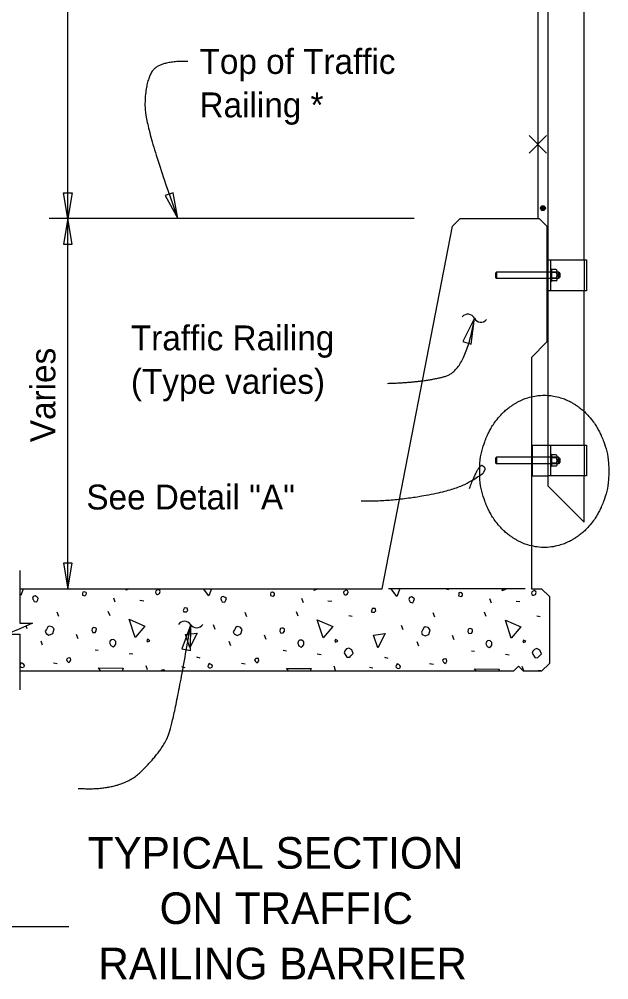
# Model space of a CAD drawing. Extents: x 0 to 41.1, y 0 to 25.9.
# Drawn here: x 29.01 to 33.79, y 11.06 to 18.84 of the extents above; entities that cross this region are included whole.
import ezdxf

# ---------------------------------------------------------------- set-up
doc = ezdxf.new("R2010")
doc.units = 0
for name, color, linetype in [('Dimension', 7, 'Continuous'), ('Miscellaneous', 7, 'Continuous'), ('SteelMisc', 7, 'Continuous'), ('SteelMisc_h', 7, 'Continuous'), ('SupstrConc', 7, 'Continuous'), ('SupstrConc_h', 7, 'Continuous'), ('TextStructures', 7, 'Continuous'), ('TrafBarrierConc', 7, 'Continuous')]:
    doc.layers.add(name, color=color, linetype=linetype)

msp = doc.modelspace()

# ---------------------------------------------------------------- linework, layer by layer
at = {"layer": 'Dimension'}
for p, q in [((29.4061, 14.2246), (29.4061, 23.2246)), ((32.214, 17.2246), (29.2561, 17.2246)), ((23.6151, 11.4901), (29.4153, 11.4901))]:
    msp.add_line(p, q, dxfattribs=at)
for points in [[(29.4061, 17.2246), (29.3708, 17.4328), (29.4413, 17.4328)], [(30.2977, 17.2246), (30.2616, 17.4327), (30.1951, 17.4092)], [(29.4061, 17.2246), (29.3708, 17.0163), (29.4413, 17.0163)], [(32.7026, 16.4167), (32.6085, 16.2276), (32.676, 16.2071)], [(29.4061, 14.2246), (29.4413, 14.4328), (29.3708, 14.4328)], [(30.403, 13.937), (30.3312, 13.7384), (30.4006, 13.7258)]]:
    msp.add_lwpolyline(points, close=True, dxfattribs=at)
msp.add_lwpolyline([(29.0176, 14.3746), (29.0176, 13.9474), (29.1209, 13.9474), (29.0176, 13.9024), (28.9142, 13.8574), (29.0176, 13.8574), (29.0176, 13.4079)], dxfattribs=at)
for centre, start, end in [((32.6489, 16.3894), 27.32823, 139.05545), ((32.7548, 16.4441), 207.32823, 319.05545), ((30.3527, 13.9038), 33.91896, 145.64618), ((30.4517, 13.9703), 213.91896, 325.64618)]:
    msp.add_arc(centre, 0.0596, start, end, dxfattribs=at)
for points, degree in [([(30.3802, 18.496), (30.1383, 18.5019), (30.0322, 18.3129), (30.0322, 17.9586), (30.2976, 17.2245)], 2), ([(31.9983, 15.889), (32.2959, 15.8977), (32.6322, 15.993), (32.7026, 16.4166)], 2), ([(33.2678, 14.5608), (33.3028, 14.5608), (33.3375, 14.5649), (33.4054, 14.5811), (33.4386, 14.5931), (33.4864, 14.6167), (33.502, 14.6255), (33.5248, 14.64), (33.5323, 14.6451), (33.5471, 14.6557), (33.5543, 14.6612), (33.5899, 14.6896), (33.6163, 14.7155), (33.6642, 14.7726), (33.6856, 14.8038), (33.7091, 14.8457), (33.7136, 14.8542), (33.7223, 14.8715), (33.7265, 14.8803), (33.7384, 14.9069), (33.7456, 14.9251), (33.7776, 15.0175), (33.7909, 15.0966), (33.7909, 15.2569), (33.7776, 15.336), (33.7456, 15.4283), (33.7384, 15.4465), (33.7265, 15.4731), (33.7223, 15.4819), (33.7136, 15.4992), (33.7091, 15.5077), (33.6856, 15.5496), (33.6642, 15.5808), (33.6163, 15.638), (33.5899, 15.6638), (33.5543, 15.6923), (33.5471, 15.6978), (33.5323, 15.7083), (33.5248, 15.7134), (33.502, 15.7279), (33.4864, 15.7367), (33.4386, 15.7603), (33.4054, 15.7724), (33.3375, 15.7885), (33.3028, 15.7926), (33.2328, 15.7926), (33.198, 15.7885), (33.1301, 15.7724), (33.097, 15.7603), (33.0492, 15.7367), (33.0336, 15.7279), (33.0108, 15.7134), (33.0033, 15.7083), (32.9885, 15.6978), (32.9812, 15.6923), (32.9456, 15.6638), (32.9193, 15.638), (32.8714, 15.5808), (32.8499, 15.5496), (32.8264, 15.5077), (32.8219, 15.4992), (32.8132, 15.4819), (32.8091, 15.4731), (32.7971, 15.4465), (32.79, 15.4283), (32.7579, 15.336), (32.7447, 15.2569), (32.7447, 15.0966), (32.7579, 15.0175), (32.79, 14.9251), (32.7971, 14.9069), (32.8091, 14.8803), (32.8132, 14.8715), (32.8219, 14.8542), (32.8264, 14.8457), (32.8499, 14.8038), (32.8714, 14.7726), (32.9193, 14.7155), (32.9456, 14.6896), (32.9812, 14.6612), (32.9885, 14.6557), (33.0033, 14.6451), (33.0108, 14.64), (33.0336, 14.6255), (33.0492, 14.6167), (33.097, 14.5931), (33.1301, 14.5811), (33.198, 14.5649), (33.2328, 14.5608), (33.2678, 14.5608)], 3), ([(31.785, 14.9372), (32.0075, 14.9325), (32.5443, 15.0224), (32.7693, 15.1547), (32.78, 15.1766), (32.7962, 15.2026), (32.737, 15.2403), (32.6589, 15.0361)], 2), ([(29.4916, 12.6094), (29.8372, 12.5861), (30.1609, 12.9013), (30.2688, 13.1436), (30.4029, 13.9374)], 2)]:
    msp.add_open_spline(points, degree=degree, dxfattribs=at)
at = {"layer": 'Miscellaneous'}
for p, q in [((33.2861, 17.8952), (33.1447, 17.7539)), ((33.1447, 17.8952), (33.2861, 17.7539)), ((33.2884, 16.8894), (33.2988, 16.8894)), ((33.292, 16.8894), (33.292, 16.6394)), ((33.2953, 16.8894), (33.2953, 16.6394)), ((33.3795, 16.7756), (33.3795, 16.7548)), ((33.3891, 16.7756), (33.3891, 16.7548)), ((33.2988, 16.6394), (33.2884, 16.6394)), ((33.1634, 15.3894), (33.1738, 15.3894)), ((33.167, 15.3894), (33.167, 15.1394)), ((33.1703, 15.3894), (33.1703, 15.1394)), ((33.3795, 15.2756), (33.3795, 15.2548)), ((33.3891, 15.2756), (33.3891, 15.2548)), ((33.1738, 15.1394), (33.1634, 15.1394)), ((30.9661, 14.2246), (30.9674, 14.2243)), ((32.4722, 14.2246), (32.4912, 14.2207)), ((29.7919, 14.1165), (29.7795, 14.15)), ((29.9916, 14.1324), (30.0234, 14.1288)), ((31.3157, 14.1129), (31.3033, 14.1465)), ((31.5154, 14.1288), (31.5473, 14.1253)), ((32.8395, 14.1094), (32.8271, 14.143)), ((33.0392, 14.1253), (33.0711, 14.1218)), ((29.334, 14.0015), (29.3199, 14.0369)), ((29.7494, 14.0068), (29.7353, 14.0422)), ((30.8578, 13.998), (30.8437, 14.0334)), ((31.2732, 14.0033), (31.2591, 14.0387)), ((31.6834, 14.0104), (31.7117, 14.0033)), ((32.3816, 13.9945), (32.3675, 14.0298)), ((32.7971, 13.9998), (32.7829, 14.0351)), ((33.2072, 14.0068), (33.2355, 13.9998)), ((29.0777, 13.9008), (29.0682, 13.9245)), ((30.6015, 13.8972), (30.5874, 13.9326)), ((32.1253, 13.8937), (32.1112, 13.9291)), ((29.4913, 13.8195), (29.4772, 13.8548)), ((31.0152, 13.8159), (31.001, 13.8513)), ((32.539, 13.8124), (32.5248, 13.8477)), ((29.2032, 13.7682), (29.1908, 13.8018)), ((30.727, 13.7647), (30.7146, 13.7983)), ((32.2508, 13.7611), (32.2384, 13.7947)), ((29.6292, 13.7311), (29.654, 13.7275)), ((29.905, 13.7028), (29.935, 13.6975)), ((31.153, 13.7275), (31.1778, 13.724)), ((31.4288, 13.6993), (31.4589, 13.694)), ((32.6769, 13.724), (32.7016, 13.7205)), ((32.9526, 13.6957), (32.9827, 13.6904)), ((29.2916, 13.6268), (29.3216, 13.6215)), ((30.4495, 13.6745), (30.4778, 13.6674)), ((30.8154, 13.6232), (30.8454, 13.6179)), ((31.9733, 13.671), (32.0016, 13.6639)), ((32.3392, 13.6197), (32.3693, 13.6144)), ((30.0535, 13.5684), (30.0411, 13.602)), ((30.3275, 13.595), (30.3558, 13.5879)), ((31.5773, 13.5649), (31.5649, 13.5985)), ((31.8513, 13.5914), (31.8796, 13.5844)), ((33.1011, 13.5614), (33.0887, 13.595))]:
    msp.add_line(p, q, dxfattribs=at)
for points in [[(33.2155, 23.2246), (33.2155, 17.2246)], [(29.0264, 14.1713), (29.0176, 14.1829)], [(29.0463, 14.2246), (29.0264, 14.1713)], [(29.1254, 14.1394), (29.1343, 14.1235), (29.1555, 14.12), (29.1643, 14.1359), (29.1678, 14.15), (29.159, 14.1589), (29.1431, 14.1677), (29.1272, 14.1624), (29.1219, 14.1465), (29.1254, 14.1394)], [(29.5249, 14.1748), (29.5444, 14.1695), (29.5567, 14.1783), (29.5585, 14.1907), (29.555, 14.1942), (29.5408, 14.2013), (29.5285, 14.1995), (29.5267, 14.1872), (29.5249, 14.1748)], [(29.8802, 14.2154), (29.8831, 14.2246)], [(29.9005, 14.2246), (29.8802, 14.2154)], [(30.1277, 14.1801), (30.1348, 14.1801), (30.1489, 14.1872), (30.1543, 14.2031), (30.1525, 14.2119), (30.1383, 14.219), (30.1207, 14.2084), (30.1171, 14.1978), (30.1207, 14.1872), (30.1277, 14.1801)], [(30.5502, 14.1677), (30.507, 14.2246)], [(30.5715, 14.2246), (30.5502, 14.1677)], [(30.6492, 14.1359), (30.6581, 14.12), (30.6793, 14.1165), (30.6881, 14.1324), (30.6917, 14.1465), (30.6828, 14.1553), (30.6669, 14.1642), (30.651, 14.1589), (30.6457, 14.143), (30.6492, 14.1359)], [(31.0487, 14.1713), (31.0682, 14.1659), (31.0806, 14.1748), (31.0823, 14.1872), (31.0788, 14.1907), (31.0647, 14.1978), (31.0523, 14.196), (31.0505, 14.1836), (31.0487, 14.1713)], [(31.4041, 14.2119), (31.408, 14.2246)], [(31.4322, 14.2246), (31.4041, 14.2119)], [(31.6516, 14.1766), (31.6586, 14.1766), (31.6728, 14.1836), (31.6781, 14.1995), (31.6763, 14.2084), (31.6622, 14.2154), (31.6445, 14.2048), (31.6409, 14.1942), (31.6445, 14.1836), (31.6516, 14.1766)], [(32.074, 14.1642), (32.0282, 14.2246)], [(32.0966, 14.2246), (32.074, 14.1642)], [(32.173, 14.1324), (32.1819, 14.1165), (32.2031, 14.1129), (32.2119, 14.1288), (32.2155, 14.143), (32.2066, 14.1518), (32.1907, 14.1606), (32.1748, 14.1553), (32.1695, 14.1394), (32.173, 14.1324)], [(32.5726, 14.1677), (32.592, 14.1624), (32.6044, 14.1713), (32.6061, 14.1836), (32.6026, 14.1872), (32.5885, 14.1942), (32.5761, 14.1925), (32.5743, 14.1801), (32.5726, 14.1677)], [(32.9279, 14.2084), (32.9329, 14.2246)], [(32.9639, 14.2246), (32.9279, 14.2084)], [(33.1754, 14.173), (33.1824, 14.173), (33.1966, 14.1801), (33.2019, 14.196), (33.2001, 14.2048), (33.186, 14.2119), (33.1683, 14.2013), (33.1648, 14.1907), (33.1683, 14.1801), (33.1754, 14.173)], [(30.3469, 14.0387), (30.3682, 14.0387), (30.3788, 14.0493), (30.3735, 14.0687), (30.3505, 14.0705), (30.3469, 14.0599), (30.3416, 14.051), (30.3469, 14.0387), (30.3434, 14.0422)], [(31.8708, 14.0351), (31.892, 14.0351), (31.9026, 14.0457), (31.8973, 14.0652), (31.8743, 14.067), (31.8708, 14.0563), (31.8654, 14.0475), (31.8708, 14.0351), (31.8672, 14.0387)], [(29.9527, 13.8318), (29.905, 13.9786), (30.0305, 13.9238), (29.9527, 13.8318)], [(31.4765, 13.8283), (31.4288, 13.975), (31.5543, 13.9202), (31.4765, 13.8283)], [(33.0004, 13.8248), (32.9526, 13.9715), (33.0781, 13.9167), (33.0004, 13.8248)], [(29.2315, 13.8637), (29.2545, 13.8513), (29.2845, 13.8637), (29.2969, 13.9008), (29.2792, 13.9185), (29.2562, 13.9238), (29.2456, 13.9167), (29.2332, 13.8972), (29.2244, 13.8813), (29.2315, 13.8637)], [(29.6009, 13.8866), (29.6098, 13.8707), (29.6292, 13.8725), (29.6381, 13.8849), (29.6398, 13.9043), (29.6275, 13.9096), (29.6186, 13.9114), (29.608, 13.9079), (29.6045, 13.9043), (29.6009, 13.8866)], [(30.3947, 13.7505), (30.3611, 13.8548), (30.4548, 13.8672), (30.3947, 13.7505)], [(30.7553, 13.8601), (30.7783, 13.8477), (30.8083, 13.8601), (30.8207, 13.8972), (30.803, 13.9149), (30.78, 13.9202), (30.7694, 13.9132), (30.7571, 13.8937), (30.7482, 13.8778), (30.7553, 13.8601)], [(31.1248, 13.8831), (31.1336, 13.8672), (31.153, 13.869), (31.1619, 13.8813), (31.1636, 13.9008), (31.1513, 13.9061), (31.1424, 13.9079), (31.1318, 13.9043), (31.1283, 13.9008), (31.1248, 13.8831)], [(31.9185, 13.747), (31.8849, 13.8513), (31.9786, 13.8637), (31.9185, 13.747)], [(32.2791, 13.8566), (32.3021, 13.8442), (32.3321, 13.8566), (32.3445, 13.8937), (32.3268, 13.9114), (32.3039, 13.9167), (32.2932, 13.9096), (32.2809, 13.8902), (32.272, 13.8743), (32.2791, 13.8566)], [(32.6486, 13.8796), (32.6574, 13.8637), (32.6769, 13.8654), (32.6857, 13.8778), (32.6875, 13.8972), (32.6751, 13.9026), (32.6662, 13.9043), (32.6556, 13.9008), (32.6521, 13.8972), (32.6486, 13.8796)], [(29.7459, 13.7876), (29.7565, 13.7664), (29.7742, 13.7558), (29.7883, 13.7664), (29.7954, 13.777), (29.7954, 13.7983), (29.7795, 13.8142), (29.76, 13.8124), (29.7512, 13.8036), (29.7459, 13.7876)], [(30.0517, 13.7965), (30.0712, 13.8053), (30.0641, 13.8124), (30.0517, 13.8177), (30.0464, 13.8053), (30.0517, 13.7965)], [(31.2697, 13.7841), (31.2803, 13.7629), (31.298, 13.7523), (31.3121, 13.7629), (31.3192, 13.7735), (31.3192, 13.7947), (31.3033, 13.8106), (31.2839, 13.8089), (31.275, 13.8), (31.2697, 13.7841)], [(31.5755, 13.7929), (31.595, 13.8018), (31.5879, 13.8089), (31.5755, 13.8142), (31.5702, 13.8018), (31.5755, 13.7929)], [(32.7935, 13.7806), (32.8041, 13.7594), (32.8218, 13.7488), (32.836, 13.7594), (32.843, 13.77), (32.843, 13.7912), (32.8271, 13.8071), (32.8077, 13.8053), (32.7988, 13.7965), (32.7935, 13.7806)], [(33.0994, 13.7894), (33.1188, 13.7983), (33.1117, 13.8053), (33.0994, 13.8106), (33.094, 13.7983), (33.0994, 13.7894)], [(31.6462, 13.7081), (31.6692, 13.671), (31.6922, 13.6727), (31.701, 13.6816), (31.7205, 13.701), (31.7081, 13.7311), (31.6834, 13.7452), (31.6657, 13.7381), (31.6516, 13.724), (31.6462, 13.7081)], [(33.1701, 13.7046), (33.193, 13.6674), (33.216, 13.6692), (33.2249, 13.678), (33.2443, 13.6975), (33.2319, 13.7275), (33.2072, 13.7417), (33.1895, 13.7346), (33.1754, 13.7205), (33.1701, 13.7046)], [(29.0282, 13.5897), (29.0406, 13.5879), (29.0529, 13.5932), (29.0565, 13.6038), (29.0512, 13.6126), (29.0406, 13.6197), (29.0282, 13.625), (29.0211, 13.6109), (29.0176, 13.6003)], [(29.403, 13.6392), (29.4136, 13.6285), (29.4242, 13.6356), (29.4312, 13.6462), (29.4277, 13.6639), (29.4189, 13.6657), (29.4065, 13.6639), (29.3959, 13.6533), (29.403, 13.6392)], [(30.552, 13.5861), (30.5644, 13.5844), (30.5767, 13.5897), (30.5803, 13.6003), (30.575, 13.6091), (30.5644, 13.6162), (30.552, 13.6215), (30.5449, 13.6073), (30.5414, 13.5967), (30.552, 13.5861)], [(30.9268, 13.6356), (30.9374, 13.625), (30.948, 13.6321), (30.955, 13.6427), (30.9515, 13.6604), (30.9427, 13.6621), (30.9303, 13.6604), (30.9197, 13.6498), (30.9268, 13.6356)], [(32.0758, 13.5826), (32.0882, 13.5808), (32.1006, 13.5861), (32.1041, 13.5967), (32.0988, 13.6056), (32.0882, 13.6126), (32.0758, 13.6179), (32.0687, 13.6038), (32.0652, 13.5932), (32.0758, 13.5826)], [(32.4506, 13.6321), (32.4612, 13.6215), (32.4718, 13.6285), (32.4789, 13.6392), (32.4753, 13.6568), (32.4665, 13.6586), (32.4541, 13.6568), (32.4435, 13.6462), (32.4506, 13.6321)], [(29.0176, 13.6003), (29.0282, 13.5897)], [(29.6759, 13.5578), (29.6557, 13.5844), (29.8555, 13.5826), (29.8462, 13.5578)], [(30.1932, 13.5578), (30.1913, 13.5669), (30.1825, 13.5687), (30.1701, 13.5669), (30.161, 13.5578)], [(31.197, 13.5578), (31.1796, 13.5808), (31.3793, 13.579), (31.3714, 13.5578)], [(32.7181, 13.5578), (32.7034, 13.5773), (32.9031, 13.5755), (32.8965, 13.5578)], [(33.2394, 13.5578), (33.239, 13.5599), (33.2301, 13.5616), (33.2178, 13.5599), (33.2157, 13.5578)]]:
    msp.add_lwpolyline(points, dxfattribs=at)
at = {"layer": 'SteelMisc'}
for p, q in [((33.2155, 23.2245), (33.2155, 17.2245)), ((33.2988, 16.8894), (33.2988, 23.2245)), ((33.5905, 16.8894), (33.5905, 23.2245)), ((33.2988, 16.6394), (33.2988, 16.8894)), ((33.2988, 16.8894), (33.6113, 16.8894)), ((33.3197, 16.8894), (33.3197, 16.6394)), ((33.6113, 16.8894), (33.6113, 16.6394)), ((33.3267, 16.8141), (33.3197, 16.8141)), ((33.3267, 16.8141), (33.3267, 16.7147)), ((33.3644, 16.8098), (33.3267, 16.8098)), ((33.3267, 16.719), (33.3267, 16.8098)), ((33.3647, 16.7871), (33.3267, 16.7871)), ((33.3647, 16.7418), (33.3267, 16.7418)), ((33.3731, 16.7303), (33.3731, 16.7985)), ((33.3844, 16.7902), (33.3731, 16.7902)), ((33.3844, 16.7387), (33.3731, 16.7387)), ((33.3844, 16.7902), (33.3844, 16.7387)), ((33.394, 16.7805), (33.3844, 16.7902)), ((33.394, 16.75), (33.3844, 16.7387)), ((33.394, 16.7805), (33.394, 16.75)), ((33.3267, 16.7147), (33.3197, 16.7147)), ((33.3644, 16.719), (33.3267, 16.719)), ((33.2988, 15.0561), (33.2988, 16.6394)), ((33.6113, 16.6394), (33.2988, 16.6394)), ((33.5905, 15.3894), (33.5905, 16.6394)), ((33.1738, 15.1394), (33.1738, 15.3894)), ((33.1738, 15.3894), (33.2988, 15.3894)), ((33.2988, 15.3894), (33.6113, 15.3894)), ((33.3197, 15.3894), (33.3197, 15.1394)), ((33.6113, 15.3894), (33.6113, 15.1394)), ((33.3267, 15.3141), (33.3197, 15.3141)), ((33.3267, 15.3141), (33.3267, 15.2147)), ((33.3644, 15.3098), (33.3267, 15.3098)), ((33.3267, 15.219), (33.3267, 15.3098)), ((33.3647, 15.2871), (33.3267, 15.2871)), ((33.3731, 15.2303), (33.3731, 15.2985)), ((33.3844, 15.2902), (33.3731, 15.2902)), ((33.3844, 15.2902), (33.3844, 15.2387)), ((33.394, 15.2805), (33.3844, 15.2902)), ((33.394, 15.25), (33.3844, 15.2387)), ((33.394, 15.2805), (33.394, 15.25)), ((33.3267, 15.2147), (33.3197, 15.2147)), ((33.3647, 15.2418), (33.3267, 15.2418)), ((33.3644, 15.219), (33.3267, 15.219)), ((33.3844, 15.2387), (33.3731, 15.2387)), ((33.1738, 15.1394), (33.2988, 15.1394)), ((33.6113, 15.1394), (33.2988, 15.1394)), ((33.5905, 14.7644), (33.5905, 15.1394))]:
    msp.add_line(p, q, dxfattribs=at)
msp.add_lwpolyline([(33.2988, 15.0561), (33.5905, 14.7644)], dxfattribs=at)
for radius in [0.0197, 0.0172, 0.0147, 0.0122, 0.00975, 0.00725, 0.00475, 0.00225]:
    msp.add_circle((33.2572, 17.3079), radius, dxfattribs=at)
for centre, radius, start, end in [((33.3613, 16.7984), 0.0118, 286.59863, 74.70054), ((33.3613, 16.7304), 0.0118, 285.15064, 73.50417), ((33.3384, 16.7644), 0.0347, 319.20147, 40.79853), ((33.3613, 15.2984), 0.0118, 286.59863, 74.70054), ((33.3384, 15.2644), 0.0347, 319.20147, 40.79853), ((33.3613, 15.2304), 0.0118, 285.15064, 73.50417)]:
    msp.add_arc(centre, radius, start, end, dxfattribs=at)
at = {"layer": 'SteelMisc_h'}
for p, q in [((33.5905, 16.8894), (33.5905, 16.6394)), ((32.8799, 16.7904), (32.8717, 16.7822)), ((32.8717, 16.7822), (32.8717, 16.7465)), ((32.8799, 16.7384), (32.8717, 16.7465)), ((33.3731, 16.7904), (32.8799, 16.7904)), ((32.8799, 16.7904), (32.8799, 16.7384)), ((33.3731, 16.7384), (32.8799, 16.7384)), ((33.5905, 15.3894), (33.5905, 15.1394)), ((33.5905, 15.3894), (33.5905, 15.1394)), ((32.8799, 15.2904), (32.8717, 15.2822)), ((32.8717, 15.2822), (32.8717, 15.2465)), ((32.8799, 15.2384), (32.8717, 15.2465)), ((33.3731, 15.2904), (32.8799, 15.2904)), ((32.8799, 15.2904), (32.8799, 15.2384)), ((33.3731, 15.2384), (32.8799, 15.2384))]:
    msp.add_line(p, q, dxfattribs=at)
at = {"layer": 'SupstrConc'}
for p, q in [((29.0176, 14.2246), (31.9551, 14.2246)), ((33.1634, 14.2246), (33.2467, 14.2246)), ((33.2467, 14.2246), (33.3092, 14.1621)), ((33.3092, 14.1621), (33.3092, 13.6204)), ((33.3092, 13.6204), (33.2467, 13.5579)), ((33.0175, 13.5579), (29.0176, 13.5579)), ((33.0175, 13.5579), (33.0592, 13.5995)), ((33.0592, 13.5995), (33.1009, 13.5579)), ((33.2467, 13.5579), (33.1009, 13.5579))]:
    msp.add_line(p, q, dxfattribs=at)
at = {"layer": 'SupstrConc_h'}
msp.add_line((33.1124, 14.2246), (32.0061, 14.2246), dxfattribs=at)
at = {"layer": 'TrafBarrierConc'}
for p, q in [((32.5244, 17.162), (32.5869, 17.2245)), ((32.5869, 17.2245), (33.2259, 17.2246)), ((33.2259, 17.2245), (33.2884, 17.162)), ((31.9551, 14.2246), (32.5244, 17.162)), ((33.2884, 17.162), (33.2884, 16.2245)), ((33.2884, 16.2245), (33.1634, 16.0995)), ((33.1634, 16.0995), (33.1634, 14.2246))]:
    msp.add_line(p, q, dxfattribs=at)

# ---------------------------------------------------------------- texts
at = {"layer": 'Dimension'}
for s, height, p in [('Top of Traffic ', 0.2016, (30.4747, 18.3949)), ('Railing *', 0.2016, (30.4747, 18.0429)), ('Traffic Railing ', 0.2016, (29.9184, 16.1562)), ('(Type varies)', 0.2016, (29.9184, 15.8042)), ('TYPICAL SECTION', 0.256001, (29.5683, 11.9589)), ('ON TRAFFIC', 0.256, (30.1511, 11.5109)), ('RAILING BARRIER', 0.256001, (29.6545, 11.0629))]:
    msp.add_text(s, height=height, dxfattribs=at).set_placement(p)
at = {"layer": 'TextStructures'}
msp.add_text('Varies', height=0.2016, rotation=90, dxfattribs=at).set_placement((29.3061, 15.4127))
msp.add_text('See Detail "A"', height=0.2016, dxfattribs=at).set_placement((29.5575, 14.8677))

doc.saveas('drawing.dxf')
